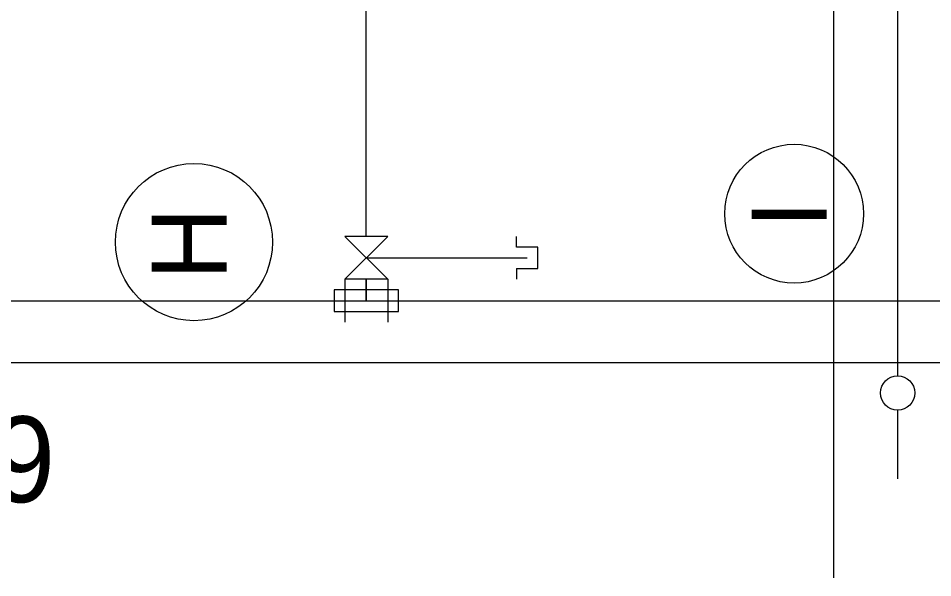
# Model space of a CAD drawing. Extents: x -264222 to -263592, y -1242345 to -1242048.
# Drawn here: x -263871.58 to -263860.91, y -1242253.37 to -1242246.85 of the extents above; entities that cross this region are included whole.
import ezdxf

# ---------------------------------------------------------------- set-up
doc = ezdxf.new("R2010")
doc.units = 0
for name, color, linetype in [('BOD_VYSKA', 7, 'Continuous'), ('HESCON_OSI_STAVBY_KFA', 7, 'Continuous'), ('KFA_2D_SITUACIA_DSP', 7, 'Continuous'), ('KFA_SO_62-1_VO_TRASA_KABLOV_PROJEKT', 7, 'Continuous')]:
    doc.layers.add(name, color=color, linetype=linetype)

msp = doc.modelspace()

# ---------------------------------------------------------------- linework, layer by layer
at = {"layer": 'HESCON_OSI_STAVBY_KFA'}
for centre, radius in [((-263862.528, -1242249.126), 0.809), ((-263869.528, -1242249.457), 0.916)]:
    msp.add_circle(centre, radius, dxfattribs=at)
at = {"layer": 'KFA_2D_SITUACIA_DSP'}
for p, q in [((-263867.518, -1242249.39), (-263867.518, -1242235.757)), ((-263861.318, -1242235.757), (-263861.321, -1242251.015)), ((-263862.068, -1242241.132), (-263862.068, -1242253.368)), ((-263867.268, -1242249.39), (-263867.768, -1242249.39)), ((-263867.768, -1242249.89), (-263867.268, -1242249.39)), ((-263867.768, -1242249.39), (-263867.268, -1242249.89)), ((-263865.768, -1242249.515), (-263865.768, -1242249.39)), ((-263865.518, -1242249.515), (-263865.768, -1242249.515)), ((-263865.518, -1242249.765), (-263865.518, -1242249.515)), ((-263867.518, -1242249.64), (-263865.643, -1242249.64)), ((-263865.768, -1242249.765), (-263865.768, -1242249.89)), ((-263865.768, -1242249.765), (-263865.518, -1242249.765)), ((-263867.268, -1242249.89), (-263867.768, -1242249.89)), ((-263867.768, -1242249.89), (-263867.768, -1242250.39)), ((-263867.518, -1242250.14), (-263867.518, -1242249.89)), ((-263867.518, -1242249.89), (-263867.518, -1242250.14)), ((-263867.268, -1242249.89), (-263867.268, -1242250.39)), ((-263867.143, -1242250.015), (-263867.893, -1242250.015)), ((-263867.893, -1242250.015), (-263867.893, -1242250.265)), ((-263867.143, -1242250.265), (-263867.143, -1242250.015)), ((-263924.143, -1242250.14), (-263788.143, -1242250.14)), ((-263867.893, -1242250.265), (-263867.143, -1242250.265)), ((-263861.321, -1242251.415), (-263861.321, -1242252.215))]:
    msp.add_line(p, q, dxfattribs=at)
msp.add_circle((-263861.321, -1242251.215), 0.2, dxfattribs=at)
at = {"layer": 'KFA_SO_62-1_VO_TRASA_KABLOV_PROJEKT'}
msp.add_line((-263856.838, -1242250.863), (-263875.838, -1242250.863), dxfattribs=at)

# ---------------------------------------------------------------- texts
at = {"layer": 'BOD_VYSKA'}
msp.add_text('237.59', height=1, dxfattribs=at).set_placement((-263875.237, -1242252.488))
at = {"layer": 'HESCON_OSI_STAVBY_KFA'}
for s, p in [('H', (-263869.147, -1242249.898)), ('I', (-263862.147, -1242249.296))]:
    msp.add_text(s, height=0.875, rotation=90, dxfattribs=at).set_placement(p)

doc.saveas('drawing.dxf')
